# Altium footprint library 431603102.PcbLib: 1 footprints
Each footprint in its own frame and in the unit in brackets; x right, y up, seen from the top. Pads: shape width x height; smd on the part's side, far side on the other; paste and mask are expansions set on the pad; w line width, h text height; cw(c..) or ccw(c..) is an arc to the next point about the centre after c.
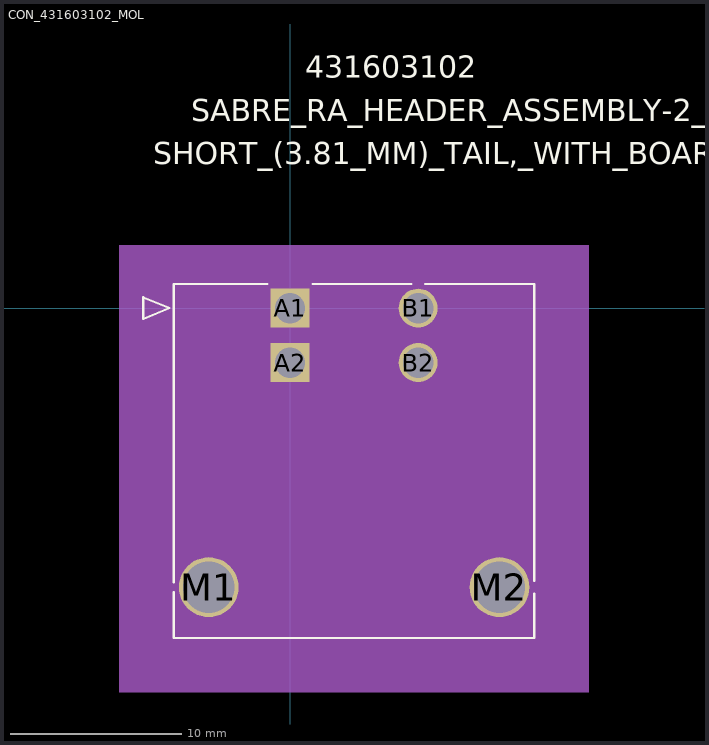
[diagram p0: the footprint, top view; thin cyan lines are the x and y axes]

## CON_431603102_MOL [mm]
pads (6):
  rect 2.28x2.28 hole 1.78 mask+0.076: A1(0,0) A2(0,-3.18)
  round 2.28 hole 1.78 mask+0.076: B1(7.493,0) B2(7.493,-3.18)
  round 3.5 hole 3 mask+0.076: M1(-4.75,-16.31) M2(12.243,-16.31)
Top Overlay:
  lines w0.127: -6.8,-16.597 -6.8,-19.272 14.28,-19.272 14.28,-16.679 ; -6.8,-16.023 -6.8,1.407 -1.316,1.407 ; 1.316,1.407 7.103,1.407 ; 7.883,1.407 14.28,1.407 14.28,-15.941 ; -8.578,-0.635 -8.578,0.635 -7.054,0 -8.578,-0.635
  text "431603102" at 0.882,13.478 h1.27
  text "SABRE_RA_HEADER_ASSEMBLY-2_CKT" at -5.785,10.938 h1.27
  text "SHORT_(3.81_MM)_TAIL,_WITH_BOARD_LOCK" at -8.008,8.398 h1.27
Mechanical 3:
  text "NOTE" at -6.8,-26.162 h1.27
  text "MAXIMUM_PACKAGE_HEIGHT:_13.39_MM" at -6.8,-28.702 h1.27
Mechanical 5:
  region: -9.975,3.683 17.455,3.683 17.455,-22.447 -9.975,-22.447
Mechanical 10:
  text "NOTE" at -6.8,-26.162 h1.27
  text "MAXIMUM_PACKAGE_HEIGHT:_13.39_MM" at -6.8,-28.702 h1.27
Mechanical 13:
  lines w0.127: -8.578,-0.635 -8.578,0.635 -7.054,0 -8.578,-0.635 ; -6.8,-19.272 14.28,-19.272 14.28,0.508 -6.8,0.508 -6.8,-19.272
  text "431603102" at 0.882,13.478 h1.27
  text "SABRE_RA_HEADER_ASSEMBLY-2_CKT" at -5.785,10.938 h1.27
  text "SHORT_(3.81_MM)_TAIL,_WITH_BOARD_LOCK" at -8.008,8.398 h1.27
Mechanical 15:
  region: 15.55,2.677 -8.07,2.677 -8.07,-20.542 15.55,-20.542
  lines w0.127: -8.07,-20.542 -8.07,2.677 15.55,2.677 15.55,-20.542 -8.07,-20.542
3D body: height 0.25, standoff 0, extent 0,0 0.254,0.254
